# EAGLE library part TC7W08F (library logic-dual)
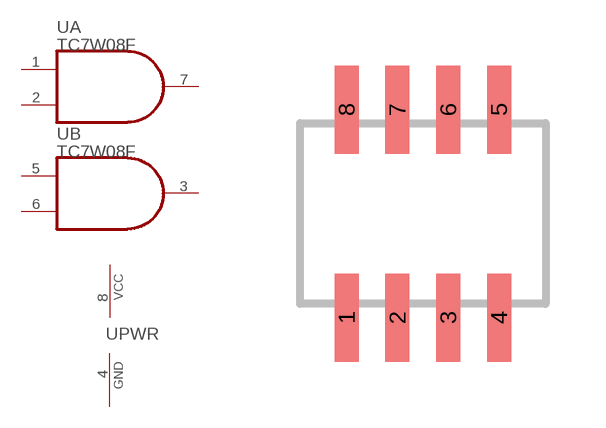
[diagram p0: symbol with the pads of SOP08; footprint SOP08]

Designator prefix U; gates A=AND B=AND PWR=PWRN

## TC7W08F-SM8  [SOP08]
1  A:I0  in
2  A:I1  in
3  B:O  out
4  PWR:GND  pas
5  B:I0  in
6  B:I1  in
7  A:O  out
8  PWR:VCC  pas

## Footprint SOP08 (pad centres in mm)
SMALL OUTLINE PACKAGE
smd 0.6 x 2.2: 1 -1.905,-2.6; 2 -0.635,-2.6; 3 0.635,-2.6; 4 1.905,-2.6; 5 1.905,2.6; 6 0.635,2.6; 7 -0.635,2.6; 8 -1.905,2.6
